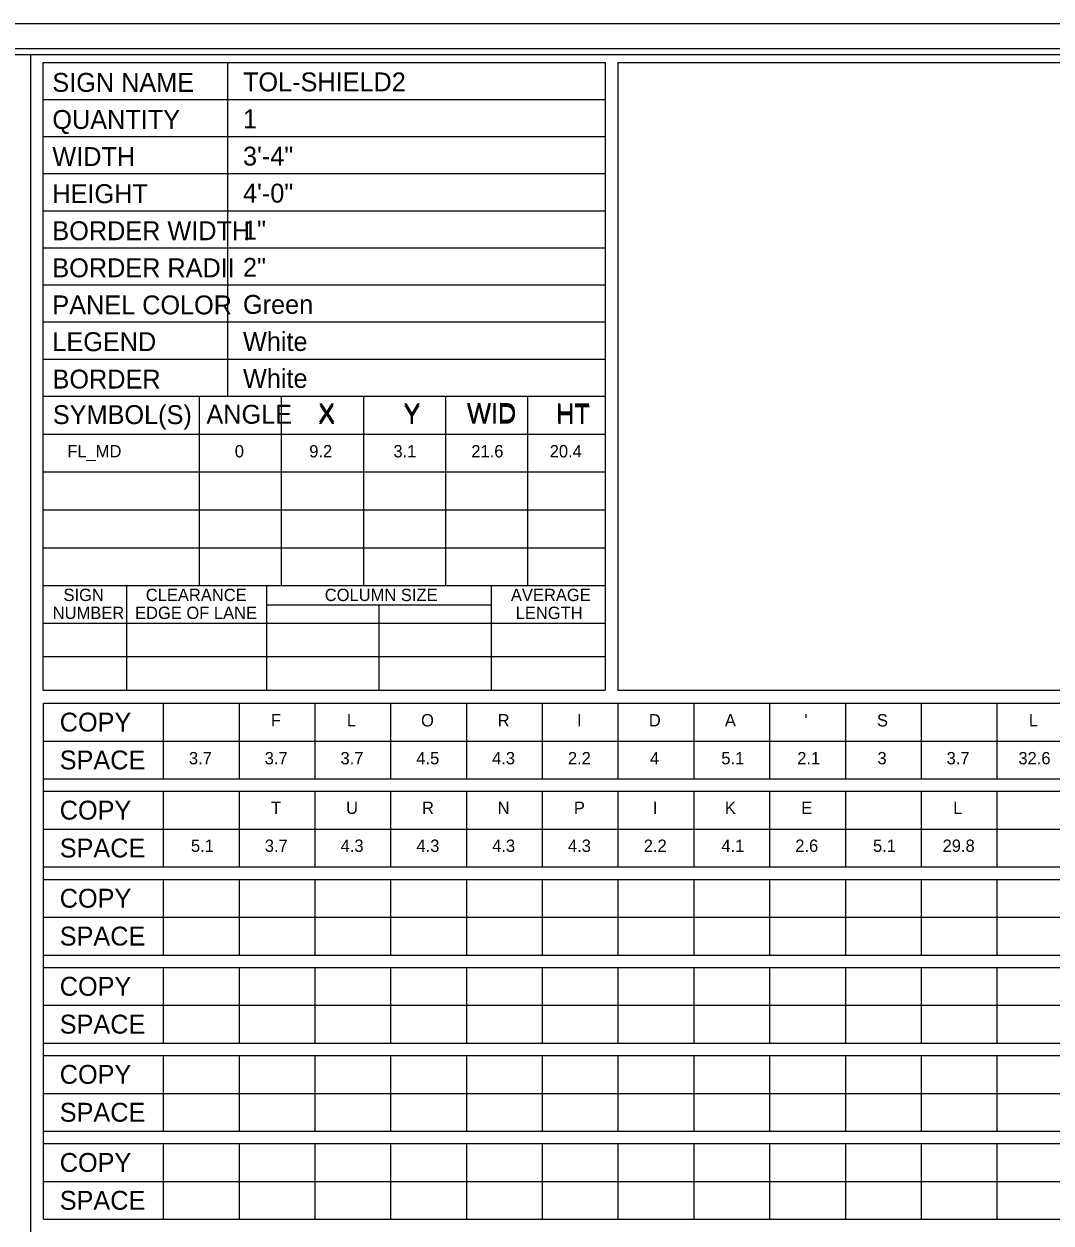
# Model space of a CAD drawing. Extents: x 17890628 to 17890844, y 17897693 to 17898031.
# Drawn here: x 17890772.14 to 17890808.4, y 17897957.5 to 17897999.81 of the extents above; entities that cross this region are included whole.
import ezdxf

# ---------------------------------------------------------------- set-up
doc = ezdxf.new("R2010")
doc.units = 0
for name, color, linetype in [('GSSign', 7, 'Continuous'), ('PlotBorder_dp', 7, 'Continuous'), ('SheetBorder_dp', 7, 'Continuous'), ('SheetLinesMisc2_dp', 7, 'Continuous'), ('TextMinor', 7, 'Continuous')]:
    doc.layers.add(name, color=color, linetype=linetype)

msp = doc.modelspace()

# ---------------------------------------------------------------- linework, layer by layer
at = {"layer": 'PlotBorder_dp'}
msp.add_lwpolyline([(17890700.471, 17897907.61), (17890843.989, 17897907.61), (17890843.989, 17897999.809), (17890700.471, 17897999.809)], close=True, dxfattribs=at)
at = {"layer": 'SheetBorder_dp'}
msp.add_line((17890705.254, 17897998.94), (17890839.205, 17897998.94), dxfattribs=at)
at = {"layer": 'SheetLinesMisc2_dp'}
for p, q in [((17890705.5, 17897998.732), (17890839.233, 17897998.732)), ((17890772.367, 17897998.732), (17890772.367, 17897915.484)), ((17890772.823, 17897976.3), (17890772.823, 17897998.455)), ((17890772.823, 17897998.455), (17890792.654, 17897998.455)), ((17890779.324, 17897998.455), (17890779.324, 17897986.674)), ((17890792.654, 17897998.455), (17890792.654, 17897976.3)), ((17890793.11, 17897998.455), (17890838.594, 17897998.455)), ((17890793.11, 17897998.455), (17890793.11, 17897976.3)), ((17890772.823, 17897997.146), (17890792.654, 17897997.146)), ((17890772.823, 17897995.837), (17890792.654, 17897995.837)), ((17890772.823, 17897994.529), (17890792.654, 17897994.529)), ((17890772.823, 17897993.22), (17890792.654, 17897993.22)), ((17890772.823, 17897991.911), (17890792.654, 17897991.911)), ((17890772.823, 17897990.603), (17890792.654, 17897990.603)), ((17890772.823, 17897989.294), (17890782.738, 17897989.294)), ((17890782.738, 17897989.294), (17890792.654, 17897989.294)), ((17890772.823, 17897987.986), (17890782.738, 17897987.986)), ((17890782.738, 17897987.986), (17890792.654, 17897987.986)), ((17890772.823, 17897986.674), (17890792.654, 17897986.674)), ((17890778.326, 17897986.674), (17890778.326, 17897979.993)), ((17890781.223, 17897986.674), (17890781.223, 17897979.993)), ((17890784.121, 17897986.674), (17890784.121, 17897979.993)), ((17890787.019, 17897986.674), (17890787.019, 17897979.993)), ((17890789.916, 17897986.674), (17890789.916, 17897979.993)), ((17890772.823, 17897985.338), (17890792.654, 17897985.338)), ((17890772.823, 17897984.002), (17890792.654, 17897984.002)), ((17890772.823, 17897982.666), (17890792.654, 17897982.666)), ((17890772.823, 17897981.329), (17890792.654, 17897981.329)), ((17890772.823, 17897979.993), (17890792.654, 17897979.993)), ((17890775.761, 17897979.993), (17890775.761, 17897976.3)), ((17890780.696, 17897979.993), (17890780.696, 17897976.3)), ((17890788.628, 17897979.993), (17890788.628, 17897976.3)), ((17890780.696, 17897979.313), (17890788.628, 17897979.313)), ((17890784.663, 17897979.313), (17890784.663, 17897976.3)), ((17890772.823, 17897978.673), (17890792.654, 17897978.673)), ((17890772.823, 17897977.487), (17890792.654, 17897977.487)), ((17890772.823, 17897976.3), (17890792.654, 17897976.3)), ((17890793.11, 17897976.3), (17890838.594, 17897976.3)), ((17890772.824, 17897957.633), (17890772.824, 17897975.843)), ((17890772.824, 17897975.843), (17890838.594, 17897975.843)), ((17890777.058, 17897975.843), (17890777.058, 17897973.171)), ((17890779.733, 17897975.843), (17890779.733, 17897973.171)), ((17890782.408, 17897975.843), (17890782.408, 17897973.171)), ((17890785.084, 17897975.843), (17890785.084, 17897973.171)), ((17890787.76, 17897975.843), (17890787.76, 17897973.171)), ((17890790.435, 17897975.843), (17890790.435, 17897973.171)), ((17890793.11, 17897975.843), (17890793.11, 17897973.171)), ((17890795.786, 17897975.843), (17890795.786, 17897973.171)), ((17890798.462, 17897975.843), (17890798.462, 17897973.171)), ((17890801.137, 17897975.843), (17890801.137, 17897973.171)), ((17890803.813, 17897975.843), (17890803.813, 17897973.171)), ((17890806.488, 17897975.843), (17890806.488, 17897973.171)), ((17890772.824, 17897974.507), (17890838.594, 17897974.507)), ((17890772.824, 17897973.171), (17890838.594, 17897973.171)), ((17890772.824, 17897972.735), (17890838.594, 17897972.735)), ((17890777.058, 17897972.735), (17890777.058, 17897970.064)), ((17890779.733, 17897972.735), (17890779.733, 17897970.064)), ((17890782.408, 17897972.735), (17890782.408, 17897970.064)), ((17890785.084, 17897972.735), (17890785.084, 17897970.064)), ((17890787.76, 17897972.735), (17890787.76, 17897970.064)), ((17890790.435, 17897972.735), (17890790.435, 17897970.064)), ((17890793.11, 17897972.735), (17890793.11, 17897970.064)), ((17890795.786, 17897972.735), (17890795.786, 17897970.064)), ((17890798.462, 17897972.735), (17890798.462, 17897970.064)), ((17890801.137, 17897972.735), (17890801.137, 17897970.064)), ((17890803.813, 17897972.735), (17890803.813, 17897970.064)), ((17890806.488, 17897972.735), (17890806.488, 17897970.064)), ((17890772.824, 17897971.399), (17890838.594, 17897971.4)), ((17890772.824, 17897970.064), (17890838.594, 17897970.064)), ((17890772.824, 17897969.628), (17890838.594, 17897969.628)), ((17890777.058, 17897969.628), (17890777.058, 17897966.956)), ((17890779.733, 17897969.628), (17890779.733, 17897966.956)), ((17890782.408, 17897969.628), (17890782.408, 17897966.956)), ((17890785.084, 17897969.628), (17890785.084, 17897966.956)), ((17890787.76, 17897969.628), (17890787.76, 17897966.956)), ((17890790.435, 17897969.628), (17890790.435, 17897966.956)), ((17890793.11, 17897969.628), (17890793.11, 17897966.956)), ((17890795.786, 17897969.628), (17890795.786, 17897966.956)), ((17890798.462, 17897969.628), (17890798.462, 17897966.956)), ((17890801.137, 17897969.628), (17890801.137, 17897966.956)), ((17890803.813, 17897969.628), (17890803.813, 17897966.956)), ((17890806.488, 17897969.628), (17890806.488, 17897966.956)), ((17890772.824, 17897968.292), (17890838.594, 17897968.292)), ((17890772.824, 17897966.956), (17890838.594, 17897966.956)), ((17890772.824, 17897966.52), (17890838.594, 17897966.52)), ((17890777.058, 17897966.52), (17890777.058, 17897963.848)), ((17890779.733, 17897966.52), (17890779.733, 17897963.848)), ((17890782.408, 17897966.52), (17890782.408, 17897963.848)), ((17890785.084, 17897966.52), (17890785.084, 17897963.848)), ((17890787.76, 17897966.52), (17890787.76, 17897963.848)), ((17890790.435, 17897966.52), (17890790.435, 17897963.848)), ((17890793.11, 17897966.52), (17890793.11, 17897963.848)), ((17890795.786, 17897966.52), (17890795.786, 17897963.848)), ((17890798.462, 17897966.52), (17890798.462, 17897963.848)), ((17890801.137, 17897966.52), (17890801.137, 17897963.848)), ((17890803.813, 17897966.52), (17890803.813, 17897963.848)), ((17890806.488, 17897966.52), (17890806.488, 17897963.848)), ((17890772.824, 17897965.184), (17890838.594, 17897965.184)), ((17890772.824, 17897963.848), (17890838.594, 17897963.848)), ((17890772.824, 17897963.412), (17890838.594, 17897963.412)), ((17890777.058, 17897963.412), (17890777.058, 17897960.74)), ((17890779.733, 17897963.412), (17890779.733, 17897960.74)), ((17890782.408, 17897963.412), (17890782.408, 17897960.74)), ((17890785.084, 17897963.412), (17890785.084, 17897960.74)), ((17890787.76, 17897963.412), (17890787.76, 17897960.74)), ((17890790.435, 17897963.412), (17890790.435, 17897960.74)), ((17890793.11, 17897963.412), (17890793.11, 17897960.74)), ((17890795.786, 17897963.412), (17890795.786, 17897960.74)), ((17890798.462, 17897963.412), (17890798.462, 17897960.74)), ((17890801.137, 17897963.412), (17890801.137, 17897960.74)), ((17890803.813, 17897963.412), (17890803.813, 17897960.74)), ((17890806.488, 17897963.412), (17890806.488, 17897960.74)), ((17890772.824, 17897962.076), (17890838.594, 17897962.076)), ((17890772.824, 17897960.74), (17890838.594, 17897960.74)), ((17890772.824, 17897960.304), (17890838.594, 17897960.304)), ((17890777.058, 17897960.304), (17890777.058, 17897957.633)), ((17890779.733, 17897960.304), (17890779.733, 17897957.633)), ((17890782.408, 17897960.304), (17890782.408, 17897957.633)), ((17890785.084, 17897960.304), (17890785.084, 17897957.633)), ((17890787.76, 17897960.304), (17890787.76, 17897957.633)), ((17890790.435, 17897960.304), (17890790.435, 17897957.633)), ((17890793.11, 17897960.304), (17890793.11, 17897957.633)), ((17890795.786, 17897960.304), (17890795.786, 17897957.633)), ((17890798.462, 17897960.304), (17890798.462, 17897957.633)), ((17890801.137, 17897960.304), (17890801.137, 17897957.633)), ((17890803.813, 17897960.304), (17890803.813, 17897957.633)), ((17890806.488, 17897960.304), (17890806.488, 17897957.633)), ((17890772.824, 17897958.969), (17890838.594, 17897958.969)), ((17890772.824, 17897957.633), (17890838.594, 17897957.633))]:
    msp.add_line(p, q, dxfattribs=at)

# ---------------------------------------------------------------- texts
at = {"layer": 'GSSign'}
for s, height, p in [('TOL-SHIELD2', 0.66667, (17890779.872, 17897997.433)), ('1', 0.667, (17890779.872, 17897996.131)), ('3\'-4"', 0.6667, (17890779.872, 17897994.815)), ('4\'-0"', 0.6667, (17890779.872, 17897993.507)), ('1"', 0.6667, (17890779.872, 17897992.198)), ('2"', 0.6667, (17890779.872, 17897990.89)), ('Green', 0.6667, (17890779.872, 17897989.581)), ('White', 0.6667, (17890779.872, 17897988.272)), ('White', 0.6667, (17890779.872, 17897986.97)), ('X', 0.667, (17890782.527, 17897985.76)), ('Y', 0.667, (17890785.54, 17897985.76)), ('WID', 0.6667, (17890787.784, 17897985.774)), ('HT', 0.6667, (17890790.924, 17897985.761)), ('FL_MD', 0.4357, (17890773.669, 17897984.516)), ('0', 0.436, (17890779.582, 17897984.516)), ('9.2', 0.4357, (17890782.211, 17897984.516)), ('3.1', 0.4357, (17890785.183, 17897984.516)), ('21.6', 0.4357, (17890787.932, 17897984.516)), ('20.4', 0.4357, (17890790.7, 17897984.516)), ('F', 0.436, (17890780.856, 17897975.023)), ('L', 0.436, (17890783.537, 17897975.023)), ('O', 0.436, (17890786.157, 17897975.023)), ('R', 0.436, (17890788.863, 17897975.023)), ('I', 0.436, (17890791.666, 17897975.023)), ('D', 0.436, (17890794.201, 17897975.023)), ('A', 0.436, (17890796.883, 17897975.023)), ("'", 0.436, (17890799.691, 17897975.023)), ('S', 0.436, (17890802.251, 17897975.023)), ('L', 0.436, (17890807.614, 17897975.023)), ('3.7', 0.4357, (17890777.963, 17897973.686)), ('3.7', 0.4357, (17890780.638, 17897973.686)), ('3.7', 0.4357, (17890783.314, 17897973.686)), ('4.5', 0.4357, (17890785.991, 17897973.686)), ('4.3', 0.4357, (17890788.666, 17897973.686)), ('2.2', 0.4357, (17890791.341, 17897973.686)), ('4', 0.436, (17890794.242, 17897973.686)), ('5.1', 0.4357, (17890796.757, 17897973.686)), ('2.1', 0.4357, (17890799.437, 17897973.686)), ('3', 0.436, (17890802.27, 17897973.686)), ('3.7', 0.4357, (17890804.71, 17897973.686)), ('32.6', 0.4357, (17890807.245, 17897973.686)), ('T', 0.436, (17890780.863, 17897971.933)), ('U', 0.436, (17890783.51, 17897971.933)), ('R', 0.436, (17890786.191, 17897971.933)), ('N', 0.436, (17890788.86, 17897971.933)), ('P', 0.436, (17890791.551, 17897971.933)), ('I', 0.436, (17890794.345, 17897971.933)), ('K', 0.436, (17890796.882, 17897971.933)), ('E', 0.436, (17890799.578, 17897971.933)), ('L', 0.436, (17890804.943, 17897971.933)), ('5.1', 0.4357, (17890778.034, 17897970.597)), ('3.7', 0.4357, (17890780.642, 17897970.597)), ('4.3', 0.4357, (17890783.319, 17897970.597)), ('4.3', 0.4357, (17890785.995, 17897970.597)), ('4.3', 0.4357, (17890788.67, 17897970.597)), ('4.3', 0.4357, (17890791.345, 17897970.597)), ('2.2', 0.4357, (17890794.02, 17897970.597)), ('4.1', 0.4357, (17890796.761, 17897970.597)), ('2.6', 0.4357, (17890799.369, 17897970.597)), ('5.1', 0.4357, (17890802.112, 17897970.597)), ('29.8', 0.4357, (17890804.569, 17897970.597))]:
    msp.add_text(s, height=height, dxfattribs=at).set_placement(p)
at = {"layer": 'TextMinor'}
for s, height, p in [('SIGN NAME', 0.6667, (17890773.142, 17897997.415)), ('QUANTITY', 0.6667, (17890773.142, 17897996.106)), ('WIDTH', 0.6667, (17890773.142, 17897994.798)), ('HEIGHT', 0.6667, (17890773.142, 17897993.489)), ('BORDER WIDTH', 0.66667, (17890773.142, 17897992.18)), ('BORDER RADII', 0.66667, (17890773.142, 17897990.872)), ('PANEL COLOR', 0.66667, (17890773.142, 17897989.563)), ('LEGEND', 0.6667, (17890773.142, 17897988.266)), ('BORDER', 0.6667, (17890773.148, 17897986.946)), ('SYMBOL(S)', 0.6667, (17890773.16, 17897985.692)), ('ANGLE', 0.6667, (17890778.581, 17897985.705)), ('X', 0.667, (17890782.527, 17897985.692)), ('Y', 0.667, (17890785.54, 17897985.692)), ('WID', 0.6667, (17890787.784, 17897985.705)), ('HT', 0.6667, (17890790.925, 17897985.693)), ('SIGN', 0.4357, (17890773.533, 17897979.448)), ('CLEARANCE', 0.4357, (17890776.44, 17897979.447)), ('COLUMN SIZE', 0.43573, (17890782.758, 17897979.447)), ('AVERAGE', 0.4357, (17890789.33, 17897979.447)), ('NUMBER', 0.4357, (17890773.154, 17897978.814)), ('EDGE OF LANE', 0.43573, (17890776.061, 17897978.814)), ('LENGTH', 0.4357, (17890789.498, 17897978.814)), ('COPY', 0.6667, (17890773.402, 17897974.843)), ('SPACE', 0.6667, (17890773.402, 17897973.507)), ('COPY', 0.6667, (17890773.402, 17897971.736)), ('SPACE', 0.6667, (17890773.402, 17897970.4)), ('COPY', 0.6667, (17890773.402, 17897968.628)), ('SPACE', 0.6667, (17890773.402, 17897967.292)), ('COPY', 0.6667, (17890773.402, 17897965.521)), ('SPACE', 0.6667, (17890773.402, 17897964.185)), ('COPY', 0.6667, (17890773.402, 17897962.413)), ('SPACE', 0.6667, (17890773.402, 17897961.076)), ('COPY', 0.6667, (17890773.402, 17897959.305)), ('SPACE', 0.6667, (17890773.402, 17897957.969))]:
    msp.add_text(s, height=height, dxfattribs=at).set_placement(p)

doc.saveas('drawing.dxf')
